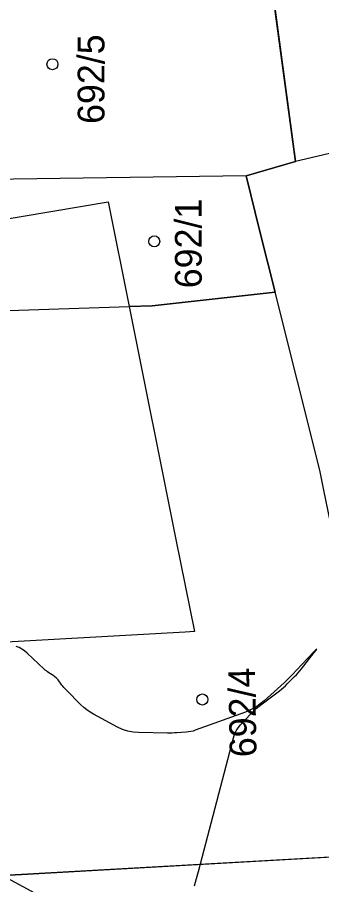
# Model space of a CAD drawing. Extents: x -534481 to -534256, y -1190577 to -1190138.
# Drawn here: x -534384.66 to -534375, y -1190505.1 to -1190477.55 of the extents above; entities that cross this region are included whole.
import ezdxf

# ---------------------------------------------------------------- set-up
doc = ezdxf.new("R2010")
doc.units = 0
for name, color, linetype in [('31', 7, 'Continuous'), ('Hranice parcel', 7, 'Continuous'), ('Parcelní čísla', 7, 'Continuous'), ('Polygon budovy', 7, 'Continuous'), ('Značky budov', 7, 'Continuous')]:
    doc.layers.add(name, color=color, linetype=linetype)

msp = doc.modelspace()

# ---------------------------------------------------------------- linework, layer by layer
at = {"layer": '31'}
msp.add_lwpolyline([(-534379.041, -1190505.138), (-534378.973, -1190504.913), (-534378.911, -1190504.687), (-534377.804, -1190500.438), (-534377.767, -1190500.326), (-534377.717, -1190500.22), (-534377.654, -1190500.121), (-534377.579, -1190500.03), (-534377.25, -1190499.678), (-534377.166, -1190499.592), (-534377.078, -1190499.51), (-534376.987, -1190499.432), (-534376.893, -1190499.358), (-534376.341, -1190498.944), (-534376.276, -1190498.893), (-534376.213, -1190498.84), (-534376.152, -1190498.785), (-534376.093, -1190498.728), (-534375.86, -1190498.495), (-534375.802, -1190498.436), (-534375.747, -1190498.375), (-534375.693, -1190498.313), (-534375.641, -1190498.249), (-534375.236, -1190497.735), (-534375.174, -1190497.654), (-534375.156, -1190497.624), (-534375.183, -1190497.646), (-534375.254, -1190497.719), (-534375.794, -1190498.293), (-534375.917, -1190498.421), (-534376.041, -1190498.546), (-534376.169, -1190498.669), (-534376.299, -1190498.789), (-534376.823, -1190499.265), (-534376.959, -1190499.376), (-534377.103, -1190499.473), (-534377.256, -1190499.555), (-534377.418, -1190499.623), (-534379.012, -1190500.202), (-534379.082, -1190500.225), (-534379.153, -1190500.242), (-534379.226, -1190500.255), (-534379.299, -1190500.263), (-534379.595, -1190500.283), (-534379.669, -1190500.287), (-534379.743, -1190500.29), (-534379.817, -1190500.291), (-534379.891, -1190500.291), (-534380.812, -1190500.276), (-534380.988, -1190500.263), (-534381.158, -1190500.229), (-534381.323, -1190500.175), (-534381.483, -1190500.101), (-534382.245, -1190499.691), (-534382.354, -1190499.627), (-534382.458, -1190499.555), (-534382.556, -1190499.476), (-534382.648, -1190499.389), (-534383.116, -1190498.915), (-534383.15, -1190498.879), (-534383.183, -1190498.842), (-534383.215, -1190498.804), (-534383.246, -1190498.765), (-534383.369, -1190498.603), (-534383.399, -1190498.567), (-534383.432, -1190498.534), (-534383.468, -1190498.503), (-534383.506, -1190498.476), (-534383.664, -1190498.372), (-534383.703, -1190498.345), (-534383.741, -1190498.317), (-534383.777, -1190498.287), (-534383.812, -1190498.256), (-534384.357, -1190497.748), (-534384.435, -1190497.682), (-534384.517, -1190497.625), (-534384.605, -1190497.576), (-534384.698, -1190497.535)], dxfattribs=at)
at = {"layer": 'Hranice parcel'}
for p, q in [((-534376.75, -1190475.31), (-534375.83, -1190482.13)), ((-534375.83, -1190482.13), (-534377.4, -1190482.59)), ((-534375.06, -1190491.94), (-534376.48, -1190486.28)), ((-534374.94, -1190492.52), (-534375.06, -1190491.94)), ((-534372.8, -1190504.12), (-534384.53, -1190504.78)), ((-534384.53, -1190504.78), (-534385.13, -1190504.81))]:
    msp.add_line(p, q, dxfattribs=at)
for points in [[(-534363.23, -1190479.17), (-534368.22, -1190480.34), (-534375.83, -1190482.13)], [(-534377.4, -1190482.59), (-534388.49, -1190482.75), (-534393.25, -1190482.82)], [(-534377.4, -1190482.59), (-534376.96, -1190484.36), (-534376.48, -1190486.28)], [(-534387.18, -1190486.94), (-534381.11, -1190486.74), (-534380.38, -1190486.72), (-534376.48, -1190486.28)], [(-534385.13, -1190504.81), (-534384.49, -1190505.16), (-534382.4, -1190506.3), (-534375.507, -1190510.084)]]:
    msp.add_lwpolyline(points, dxfattribs=at)
at = {"layer": 'Polygon budovy'}
for points in [[(-534389.45, -1190477.08), (-534389.41, -1190477.39), (-534388.49, -1190482.75), (-534388.19, -1190484.49), (-534381.78, -1190483.41), (-534381.11, -1190486.74), (-534380.38, -1190486.72), (-534376.48, -1190486.28), (-534376.96, -1190484.36), (-534377.4, -1190482.59), (-534375.83, -1190482.13), (-534376.75, -1190475.31), (-534382.56, -1190476.12)], [(-534381.11, -1190486.74), (-534379.63, -1190494.14), (-534379.04, -1190497.06), (-534379.33, -1190497.08), (-534385.97, -1190497.46), (-534389.82, -1190497.69), (-534389.86, -1190498.78), (-534389.63, -1190505.06), (-534385.13, -1190504.81), (-534384.53, -1190504.78), (-534372.8, -1190504.12), (-534374.01, -1190497.07), (-534374.08, -1190496.69), (-534374.94, -1190492.52), (-534375.06, -1190491.94), (-534376.48, -1190486.28), (-534380.38, -1190486.72)]]:
    msp.add_lwpolyline(points, close=True, dxfattribs=at)
at = {"layer": 'Značky budov'}
for centre in [(-534383.548, -1190479.042), (-534380.316, -1190484.67), (-534378.789, -1190499.223)]:
    msp.add_circle(centre, 0.175, dxfattribs=at)

# ---------------------------------------------------------------- texts
at = {"layer": 'Parcelní čísla'}
for s, rotation, p in [('692/5', 90, (-534381.897, -1190480.94)), ('692/1', 90, (-534378.808, -1190486.16)), ('692/4', 91, (-534377.066, -1190501.048))]:
    msp.add_text(s, height=0.85, rotation=rotation, dxfattribs=at).set_placement(p)

doc.saveas('drawing.dxf')
